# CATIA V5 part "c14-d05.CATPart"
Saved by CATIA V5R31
Part number: Part1
Bounding box of the stored display mesh (mm): x -55 to 55, y -96.632 to 96.632, z -25 to 65
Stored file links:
  D:\PROJECTS\Project 2021\US EDITION\CATIA V5 6R 2021\Resources\Part Files\c14_catia_v5_6r2021_prt\c14-catia-v5-6r2021-figr-14-18\c14-d05.CATPart
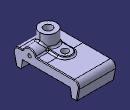
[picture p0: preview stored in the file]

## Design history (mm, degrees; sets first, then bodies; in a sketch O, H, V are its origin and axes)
Body1 (main body)
  Sketch1 on yz-plane, origin (0, 0, 0), H (0, 0, -1), V (0, 1, 0)
    construction line L1 (-49.4514, 0) -> (56.6299, 0)
    line L2 (0, 0) -> (0, 70.5918)
    point P3 (25, 75)
    line L3 (25, 75) -> (25, 90)
    point P4 (25, 90)
    line L4 (25, 90) -> (-25, 100)
    point P5 (-25, 100)
    line L5 (-25, 100) -> (-25, 0)
    point P6 (-25, 0)
    point P7 (0, 0)
    construction line L6 through (0, 0) direction (-1, 0)
    point P10 (25, -75)
    point P11 (25, -90)
    point P12 (-25, -100)
    point P13 (-25, 0)
    line L7 (0, 0) -> (0, -70.5918)
    line L8 (25, -75) -> (25, -90)
    line L9 (25, -90) -> (-25, -100)
    line L10 (-25, -100) -> (-25, 0)
    line L11 (25, 75) -> (0, 70.5918)
    point P14 (0, 70.5918)
    point P15 (0, -70.5918)
    point P16 (25, -75)
    line L12 (25, -75) -> (0, -70.5918)
    axis line L13 (25, 75) -> (-31.7388, 75)
    distance P5 P12 = 200
    length L3 = 15
    angle L11 L13 = 10
    distance L3 L5 = 50
    distance P3 P10 = 150
    angle L5 L6 = 270 (reference)
    coincidence: P6 L1, O P7, P6 P13, P10 P16
    symmetry: O P7 L1, P3 P10 L1, P4 P11 L1, P5 P12 L1, P6 P13 L1, L2 L7 L1, L3 L8 L1, L4 L9 L1, L5 L10 L1, P14 P15 L1, P3 P16 L1, L11 L12 L1
  Pad1: profile Sketch1, direction (1, 0, 0), length 55, mirrored extent
  Sketch2 on face of Pad1, origin (55, 0, 0), H (0, 1, 0), V (0, 0, 1)
    arc A1 centre (-50, 20) radius 20 from (-30.6351, 25) to (-69.3649, 25) ccw
    point P1 (-50, 20)
    line L1 (-69.3649, 25) -> (-30.6351, 25)
    reference projected line E1 (0, 25) -> (-100, 25) from edge [face of Pad1 | face of Pad1]
    reference projected point E2 (-100, 25) from vertex [face of Pad1 | face of Pad1 | face of Pad1]
    reference projected line E3 (0, 25) -> (-100, 25) from edge [face of Pad1 | face of Pad1]
    radius A1 = 20
    distance P1 E2 H = 50
    distance P1 E3 = 5
    horizontal: L1 H
    coincidence: L1 E1
  Pad2: profile Sketch2, direction (-1, 0, 0), length 55
  Sketch3 on face of Pad1, origin (0, 0, 25), H (1, 0, 0), V (0, 1, 0)
    circle A1 centre (0, -50) radius 25
    point P1 (0, -50)
    point P2 (0, -25)
    radius A1 = 25
    distance P1 H = 50
    coincidence: P1 V, A1 P2, P2 V
  Pad3: profile Sketch3, direction (0, 0, 1), length 40
  Sketch4 on face of Pad1, origin (0, 0, 25), H (1, 0, 0), V (0, 1, 0)
    line L1 (-20, -50) -> (-20, 0)
    point P2 (-20, 0)
    arc A1 centre (0, 0) radius 20 from (-20, 0) to (20, 0) cw
    point P3 (0, 0)
    line L2 (20, 0) -> (20, -50)
    line L3 (20, -50) -> (-20, -50)
    distance P3 L3 = 50
    radius A1 = 20
    coincidence: P2 H, P3 O
    vertical: L1 V, L2 V
    tangency: A1 L1, L2 A1
    horizontal: L3 H
  Pad4: profile Sketch4, direction (0, 0, 1), length 5
  Fillet1: radius 15, on edge [face of Pad1 | face of Pad1] (x2)
  Fillet2: radius 5, on edge [face of Pad1 | face of Pad4]
  Fillet3: radius 2, on edge [face of Pad4 | face of Fillet2]
  Fillet4: radius 5, on edge [face of Pad1 | face of Pad2]
  Fillet5: radius 5, on edge [face of Pad2 | face of Pad1]
  Fillet6: radius 5, on edge [face of Pad2 | face of Pad3]
  Fillet7: radius 2, on edge [face of Pad1 | face of Fillet1]; 1 edge
  Sketch5 on face of Pad1, origin (55, -45.7053, 34.0838), H (0, 1, 0), V (0, 0, 1)
    point P1 (-4.2947, -14.0838)
    reference projected arc E1 centre (-4.2947, -14.0838) radius 20 from (15.0702, -9.0838) to (-23.6596, -9.0838) ccw from edge of Pad2
    concentricity: P1 E1
  Hole1: placed by Sketch5, at (55, -50, 20) direction (-1, 0, 0), diameter 10, depth 20
  Sketch6 on face of Pad3, origin (0, -50, 65), H (1, 0, 0), V (0, 1, 0)
    point P1 (0, 0)
    reference projected circle E1 centre (0, 0) radius 25 from edge [face of Pad3 | face of Pad3]
    concentricity: P1 E1
  Hole2: placed by Sketch6, at (0, -50, 65) direction (0, 0, -1), diameter 25, through (limit type 3)
  Sketch7 on face of Pad4, origin (-2.136, -9.3115, 30), H (1, 0, 0), V (0, 1, 0)
    point P1 (2.136, 9.3115)
    reference projected arc E1 centre (2.136, 9.3115) radius 18.2918 from (20.4278, 9.3115) to (-16.1558, 9.3115) ccw from edge [face of Pad4 | face of Fillet3]
    concentricity: P1 E1
  Hole3: placed by Sketch7, at (0, 0, 30) direction (0, 0, -1), diameter 20, through (limit type 3)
